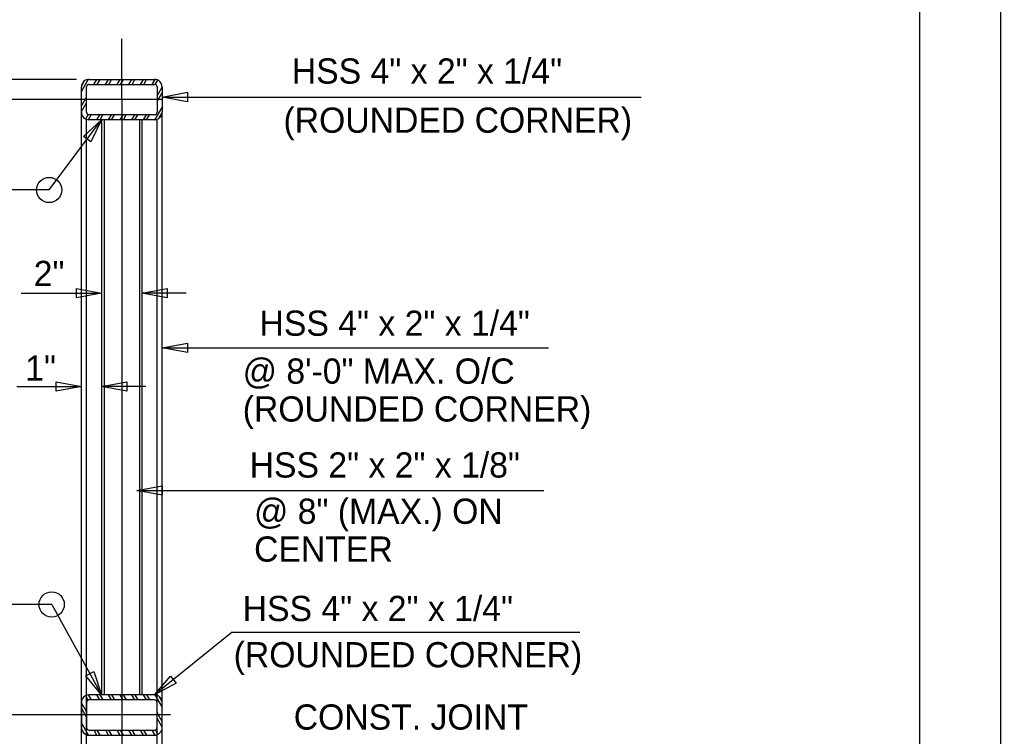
# Model space of a CAD drawing. Extents: x 0 to 22.7, y 0 to 15.8.
# Drawn here: x 18.617 to 22.667, y 9.871 to 12.831 of the extents above; entities that cross this region are included whole.
import ezdxf

# ---------------------------------------------------------------- set-up
doc = ezdxf.new("R2010")
doc.units = 0
for name, color, linetype in [('BORDER_ANNO_Cutsheet', 7, 'Continuous'), ('BRDG_ANNO_Anno-Sheet', 7, 'Continuous'), ('BRDG_ANNO_General-Notes', 7, 'Continuous'), ('BRDG_BASE_Dtlctrln', 7, 'Continuous'), ('BRDG_BASE_Hidden-Line', 7, 'Continuous'), ('BRDG_BASE_Obj-Line', 7, 'Continuous'), ('BRDG_BASE_Pattern', 7, 'Continuous'), ('Default', 7, 'Continuous')]:
    doc.layers.add(name, color=color, linetype=linetype)

# ---------------------------------------------------------------- blocks, each defined once
blk = doc.blocks.new('TERM')
at = {"layer": 'Default'}
for p, q in [((-1.6, -0.267), (-1.6, 0.267)), ((-1.6, 0.267), (0, 0)), ((0, 0), (-1.6, -0.267))]:
    blk.add_line(p, q, dxfattribs=at)

msp = doc.modelspace()

# ---------------------------------------------------------------- linework, layer by layer
at = {"layer": 'BORDER_ANNO_Cutsheet'}
msp.add_lwpolyline([(0, 14.6667), (22.6667, 14.6667), (22.6667, 0), (0, 0)], close=True, dxfattribs=at)
at = {"layer": 'BRDG_ANNO_Anno-Sheet'}
msp.add_lwpolyline([(1, 14.3333), (22.3333, 14.3333), (22.3333, 0.3333), (1, 0.3333)], close=True, dxfattribs=at)
at = {"layer": 'BRDG_ANNO_General-Notes'}
for p, q in [((18.8515, 12.5839), (16.936, 12.5839)), ((19.2057, 12.5109), (21.1832, 12.5109)), ((18.7392, 12.127), (18.9557, 12.4172)), ((18.8808, 12.3482), (18.9557, 12.4172)), ((18.9557, 12.4172), (18.9109, 12.3258)), ((18.9109, 12.3258), (18.8808, 12.3482)), ((18.7392, 12.127), (17.9892, 12.127)), ((18.6234, 11.7012), (18.9557, 11.7012)), ((19.3046, 11.7012), (19.1223, 11.7012)), ((19.2057, 11.4749), (20.8015, 11.4749)), ((18.6052, 11.3156), (18.8723, 11.3156)), ((19.138, 11.3156), (18.9557, 11.3156)), ((19.1015, 10.8859), (20.7822, 10.8859)), ((18.7495, 10.4154), (17.9995, 10.4154)), ((18.7495, 10.4154), (18.9557, 10.0422)), ((19.4944, 10.3004), (19.1744, 10.0422)), ((19.4944, 10.3004), (20.9305, 10.3004)), ((18.8909, 10.1207), (18.9237, 10.1388)), ((18.9237, 10.1388), (18.9557, 10.0422)), ((18.9557, 10.0422), (18.8909, 10.1207)), ((19.1744, 10.0422), (19.2405, 10.1196)), ((19.264, 10.0904), (19.1744, 10.0422)), ((19.2405, 10.1196), (19.264, 10.0904))]:
    msp.add_line(p, q, dxfattribs=at)
for centre in [(18.7392, 12.127), (18.7495, 10.4154)]:
    msp.add_circle(centre, 0.0521, dxfattribs=at)
at = {"layer": 'BRDG_BASE_Dtlctrln'}
for p, q in [((19.039, 12.5005), (19.039, 12.7505)), ((19.039, 12.5005), (17.2778, 12.5005)), ((19.039, 12.5005), (19.039, 9.9589)), ((19.2057, 12.5005), (19.039, 12.5005)), ((19.039, 9.9589), (17.2778, 9.9589)), ((19.039, 9.9589), (19.039, 9.5839)), ((19.2403, 9.9589), (19.039, 9.9589))]:
    msp.add_line(p, q, dxfattribs=at)
at = {"layer": 'BRDG_BASE_Hidden-Line'}
for p, q in [((18.8932, 9.6255), (18.8932, 12.4172)), ((18.9661, 12.4172), (18.9661, 10.0422)), ((19.1119, 12.4172), (19.1119, 10.0422)), ((19.1848, 9.6255), (19.1848, 12.419))]:
    msp.add_line(p, q, dxfattribs=at)
at = {"layer": 'BRDG_BASE_Obj-Line'}
for p, q in [((18.9036, 12.5839), (19.1744, 12.5839)), ((18.9036, 12.563), (19.1744, 12.563)), ((18.8723, 12.4484), (18.8723, 12.5526)), ((18.8932, 12.4484), (18.8932, 12.5526)), ((19.1848, 12.5526), (19.1848, 12.4484)), ((19.2057, 12.5526), (19.2057, 12.4484)), ((18.8723, 9.7074), (18.8723, 12.4484)), ((19.1744, 12.438), (18.9036, 12.438)), ((19.2057, 9.7074), (19.2057, 12.4484)), ((19.1744, 12.4172), (18.9036, 12.4172)), ((18.9557, 12.4172), (18.9557, 10.0422)), ((19.1223, 12.4172), (19.1223, 10.0422)), ((18.8723, 10.0109), (18.8723, 9.9068)), ((18.8932, 10.0109), (18.8932, 9.9068)), ((19.1744, 10.0422), (18.9036, 10.0422)), ((19.1744, 10.0214), (18.9036, 10.0214)), ((19.1848, 9.9068), (19.1848, 10.0109)), ((19.2057, 9.9068), (19.2057, 10.0109)), ((18.9036, 9.8964), (19.1744, 9.8964)), ((18.9036, 9.8755), (19.1744, 9.8755))]:
    msp.add_line(p, q, dxfattribs=at)
for centre, radius, start, end in [((18.9036, 12.5526), 0.0312, 90, 180), ((18.9036, 12.5526), 0.0104, 90, 180), ((19.1744, 12.5526), 0.0312, 0, 90), ((19.1744, 12.5526), 0.0104, 0, 90), ((18.9036, 12.4484), 0.0312, 180, 270), ((18.9036, 12.4484), 0.0104, 180, 270), ((19.1744, 12.4484), 0.0104, 270, 360), ((19.1744, 12.4484), 0.0312, 270, 360), ((18.9036, 10.0109), 0.0312, 90, 180), ((18.9036, 10.0109), 0.0104, 90, 180), ((19.1745, 10.0109), 0.0312, 0, 90), ((19.1745, 10.0109), 0.0104, 0, 90), ((18.9036, 9.9068), 0.0312, 180, 270), ((18.9036, 9.9068), 0.0104, 180, 270), ((19.1745, 9.9068), 0.0104, 270, 360), ((19.1745, 9.9068), 0.0312, 270, 360)]:
    msp.add_arc(centre, radius, start, end, dxfattribs=at)
at = {"layer": 'BRDG_BASE_Pattern'}
for p, q in [((18.8723, 12.5342), (18.9008, 12.5835)), ((18.8734, 12.5589), (18.883, 12.5756)), ((18.9239, 12.563), (18.9359, 12.5839)), ((18.9371, 12.563), (18.9491, 12.5839)), ((18.972, 12.563), (18.984, 12.5839)), ((18.9852, 12.563), (18.9972, 12.5839)), ((19.0201, 12.563), (19.0321, 12.5839)), ((19.0333, 12.563), (19.0454, 12.5839)), ((19.0682, 12.563), (19.0803, 12.5839)), ((19.0815, 12.563), (19.0934, 12.5839)), ((19.1163, 12.563), (19.1283, 12.5839)), ((19.1295, 12.563), (19.1416, 12.5839)), ((19.1644, 12.563), (19.1763, 12.5835)), ((19.1772, 12.5622), (19.1877, 12.5805)), ((19.1848, 12.5151), (19.2057, 12.5511)), ((19.1848, 12.4921), (19.2057, 12.5282)), ((18.8723, 12.4738), (18.8932, 12.5098)), ((18.8723, 12.4509), (18.8932, 12.487)), ((18.8899, 12.4208), (18.9004, 12.439)), ((18.9013, 12.4176), (18.913, 12.438)), ((18.9359, 12.4172), (18.9479, 12.438)), ((18.9491, 12.4172), (18.9611, 12.438)), ((18.984, 12.4172), (18.996, 12.438)), ((18.9972, 12.4172), (19.0093, 12.438)), ((19.0321, 12.4172), (19.0442, 12.438)), ((19.0454, 12.4172), (19.0574, 12.438)), ((19.0803, 12.4172), (19.0923, 12.438)), ((19.0934, 12.4172), (19.1055, 12.438)), ((19.1283, 12.4172), (19.1404, 12.438)), ((19.1416, 12.4172), (19.1536, 12.438)), ((19.1766, 12.4175), (19.2057, 12.4678)), ((19.1938, 12.4243), (19.2048, 12.4435)), ((18.8932, 9.9734), (18.8723, 10.0095)), ((18.9008, 10.0206), (18.8903, 10.0388)), ((18.9136, 10.0214), (18.9017, 10.0419)), ((18.9485, 10.0214), (18.9365, 10.0422)), ((18.9617, 10.0214), (18.9497, 10.0422)), ((18.9966, 10.0214), (18.9846, 10.0422)), ((19.0098, 10.0214), (18.9978, 10.0422)), ((19.0447, 10.0214), (19.0327, 10.0422)), ((19.0579, 10.0214), (19.0459, 10.0422)), ((19.0928, 10.0214), (19.0808, 10.0422)), ((19.106, 10.0214), (19.094, 10.0422)), ((19.1409, 10.0214), (19.1289, 10.0422)), ((19.1542, 10.0214), (19.1421, 10.0422)), ((19.2057, 9.9926), (19.1772, 10.0418)), ((19.2046, 10.0172), (19.195, 10.0339)), ((18.8932, 9.9505), (18.8723, 9.9866)), ((19.2057, 9.9321), (19.1848, 9.9682)), ((18.9014, 9.8758), (18.8723, 9.9261)), ((19.2057, 9.9092), (19.1848, 9.9453)), ((18.8842, 9.8827), (18.8732, 9.9018)), ((18.9365, 9.8755), (18.9244, 9.8964)), ((18.9497, 9.8755), (18.9377, 9.8964)), ((18.9846, 9.8755), (18.9726, 9.8964)), ((18.9978, 9.8755), (18.9857, 9.8964)), ((19.0327, 9.8755), (19.0206, 9.8964)), ((19.0459, 9.8755), (19.0339, 9.8964)), ((19.0808, 9.8755), (19.0687, 9.8964)), ((19.094, 9.8755), (19.082, 9.8964)), ((19.1289, 9.8755), (19.1169, 9.8964)), ((19.1421, 9.8755), (19.1301, 9.8964)), ((19.1768, 9.8759), (19.165, 9.8964)), ((19.1881, 9.8792), (19.1777, 9.8973))]:
    msp.add_line(p, q, dxfattribs=at)

# ---------------------------------------------------------------- block references
at = {"layer": 'BRDG_ANNO_General-Notes', "xscale": 0.06510416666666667, "yscale": 0.0732421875, "rotation": 180}
for p in [(19.2057, 12.5109), (19.1223, 11.7012), (19.2057, 11.4749), (18.9557, 11.3156), (19.1015, 10.8859)]:
    msp.add_blockref('TERM', p, dxfattribs=at)
at = {"layer": 'BRDG_ANNO_General-Notes', "xscale": 0.06510416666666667, "yscale": 0.0732421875}
for p in [(18.9557, 11.7012), (18.8723, 11.3156)]:
    msp.add_blockref('TERM', p, dxfattribs=at)

# ---------------------------------------------------------------- texts
at = {"layer": 'BRDG_ANNO_General-Notes'}
for s, height, p in [('HSS 4" x 2" x 1/4"', 0.104167, (19.741, 12.5662)), ('(ROUNDED CORNER)', 0.104167, (19.7066, 12.3633)), ('2"', 0.10417, (18.6754, 11.7302)), ('HSS 4" x 2" x 1/4"', 0.104167, (19.6077, 11.5248)), ('1"', 0.10417, (18.6404, 11.3394)), ('@ 8\'-0" MAX. O/C', 0.104167, (19.5383, 11.327)), ('(ROUNDED CORNER)', 0.104167, (19.5383, 11.1707)), ('HSS 2" x 2" x 1/8"', 0.104167, (19.5668, 10.9394)), ('@ 8" (MAX.) ON', 0.104167, (19.5852, 10.7483)), ('CENTER', 0.10417, (19.5852, 10.5921)), ('HSS 4" x 2" x 1/4"', 0.104167, (19.5382, 10.3467)), ('(ROUNDED CORNER)', 0.104167, (19.5008, 10.1558)), ('CONST. JOINT', 0.104167, (19.7489, 9.8985))]:
    msp.add_text(s, height=height, dxfattribs=at).set_placement(p)

doc.saveas('drawing.dxf')
